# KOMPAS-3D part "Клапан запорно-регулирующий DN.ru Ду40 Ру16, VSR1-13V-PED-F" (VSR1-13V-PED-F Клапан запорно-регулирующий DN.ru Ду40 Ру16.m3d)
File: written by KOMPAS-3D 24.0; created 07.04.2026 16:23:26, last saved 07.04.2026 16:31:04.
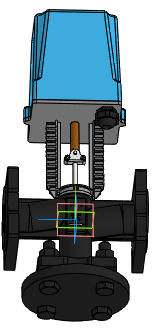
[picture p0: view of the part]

Document properties: Автор: R2D2; Полное имя файла: E:\Работа\Зайцев\Солянка\VSR1-13V-PED-F Клапан запорно-регулирующий DN.ru\DN40\VSR1-13V-PED-F Клапан запорно-регулирующий DN.ru Ду40 Ру16.m3d

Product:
- Part/product: Клапан запорно-регулирующий DN.ru Ду40 Ру16  | designation VSR1-13V-PED-F
    Масса: 10.5
    Раздел спецификации: Прочие изделия
    Примечание: D090-02890

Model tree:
1. Операция без истории:1  (labels: SHAPEOBJECT3D_ATTR_BUTT)

Expressions: VSR1-13V-PED-F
